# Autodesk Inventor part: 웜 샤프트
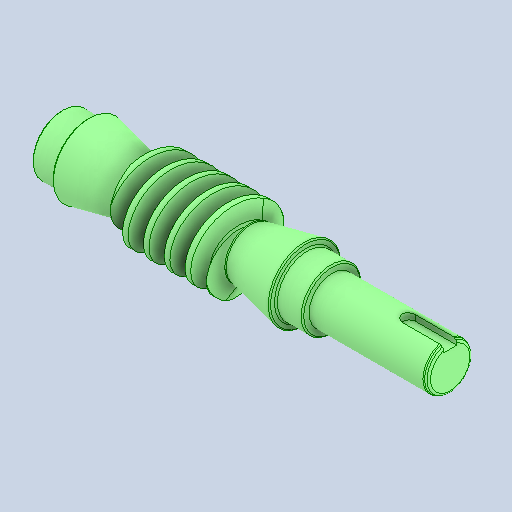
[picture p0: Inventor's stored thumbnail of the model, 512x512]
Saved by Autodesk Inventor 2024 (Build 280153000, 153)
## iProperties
Created: 2025-05
Part Number: 웜 샤프트
Material: 탄소강
Document SubType Name: Modeling
Designer: 11
Density: 7.87 g/cm^3
Appearance: 기본값
Author: jhkim
Sending System: Autodesk Inventor 2026
Preprocessor: ST-DEVELOPER v20.1
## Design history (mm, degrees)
node "웜 샤프트1"
node "솔리드1"
body "Solid1"
